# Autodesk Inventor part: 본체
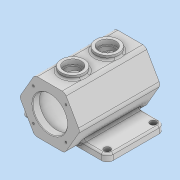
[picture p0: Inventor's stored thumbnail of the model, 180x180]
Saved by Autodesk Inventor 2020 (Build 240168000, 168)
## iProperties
Created: 2021-06
Part Number: 본체
Material: 일반
Document SubType Name: Modeling
Designer: MIRAE
Density: 1 g/cm^3
Appearance: 기본값
Mass: 553.662 g
Surface Area: 1102.91 cm^2
Volume: 553.662 cm^3
Author: MIRAE
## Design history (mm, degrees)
sketch "스케치5"
  geometry: L1 (0, 70)-(52.5, 70); L2 (52.5, 70)-(52.5, -70); L3 (52.5, -70)-(0, -70); L4 (0, -70)-(0, 70); L5 (30, 70)-(30, 58); L6 (30, 58)-(37.5, 58); L7 (37.5, 58)-(37.5, -58); L8 (37.5, -58)-(30, -58); L9 (30, -58)-(30, -70); 2 further points
  constraints: 18 end point, 4 perpendicular, 4 point on line, 2 parallel, 1 coincident, 1 horizontal, 1 midpoint, 1 vertical
  dimensions: "d13" = 105 diameter of L2 L4; "d14" = 140 distance of L1.end L2.end; "d15" = 60 diameter of L5 L4; "d16" = 75 diameter of L7 L4; "d17" = 12 distance between parallel lines of L6 L1; "d18" = 12 distance between parallel lines of L3 L8
revolve "회전2" sketch "스케치5" stored, may be unused: angle "d19" = 90 deg
sketch "스케치6" dims "d20" = 105
  geometry: L1 (52.5, 0)-(26.25, -45.466); L2 (26.25, -45.466)-(-26.25, -45.466); L3 (-26.25, -45.466)-(-52.5, 0); L4 (-52.5, 0)-(-26.25, 45.466); L5 (-26.25, 45.466)-(26.25, 45.466); L6 (26.25, 45.466)-(52.5, 0); C1 r 52.5 at (0, 0) reference; 13 further points
  constraints: 12 end point, 2 coincident, 1 horizontal, 16 other
extrude "돌출2" cut sketch "스케치6" extent not by distance; stored distance "d21" = 0; taper "d22" = 0 deg
node "작업 평면1"
sketch "스케치7"
  geometry: L1 (75, 45)-(-75, 45); L2 (-75, 45)-(-75, -55); L3 (-75, -55)-(75, -55); L4 (75, -55)-(75, 45); L5 (75, 45)-(-75, -55); L6 (-75, 45)-(75, -55); L7 (-26.25, 70)-(26.25, 70) reference; 3 further points
  constraints: 12 end point, 3 midpoint, 2 parallel, 1 horizontal, 1 perpendicular, 1 vertical alignment
  dimensions: "d24" = 150 distance of L3.end L2.end; "d25" = 100 distance of L2.end L1.end; "d26" = 25 distance between parallel lines of L7 L1
extrude "돌출3" join sketch "스케치7" distance "d27" = 12; taper "d28" = 0 deg
sketch "스케치10"
  geometry: L1 (26.25, -45.466)-(54.534, -17.182); L2 (26.25, -45.466)-(66.25, -45.466); C1 r 40 at (26.25, -45.466); 2 further points
  constraints: 4 end point, 2 coincident, 1 centre point, 1 equal length, 1 horizontal
  dimensions: "d43" = 80 diameter of C1; "d44" = 40 distance of L1.start L1.end; "d45" = 45 deg angle of L2 L1
hole "구멍2" sketch "스케치10" at (54.534, -17.182) diameter "d46" = 3.45873; stored, may be unused: countersink angle "d50" = 90 deg, drill point angle "d52" = 118 deg; dims "d47" = 8, "d48" = 30, "d49" = 8, "d51" = 10
sketch "스케치11" dims "d56" = 80
  geometry: L1 (26.25, 45.466)-(26.25, 85.466); 2 further points
  constraints: 2 coincident, 2 end point, 1 vertical, 1 vertical alignment, 2 other
hole "구멍3" sketch "스케치11" at (26.25, 85.466) diameter "d57" = 3.45873; stored, may be unused: countersink angle "d61" = 90 deg, drill point angle "d63" = 118 deg; dims "d58" = 8, "d59" = 30, "d60" = 8, "d62" = 10
fillet "모깎기1" dims "d67" = 10
sketch "스케치12"
  geometry: L1 (-58.005, 25.503)-(-58.005, -15.503); L2 (-58.005, -15.503)-(-63.995, -15.503); L3 (-63.995, -15.503)-(-63.995, 25.503); L4 (-63.995, 25.503)-(-58.005, 25.503); L5 (-58.005, 25.503)-(-63.995, -15.503); L6 (-65, -45)-(65, -45) reference; L7 (-75, 45)-(-75, -35) reference; 2 further points
  constraints: 2 end point, 1 midpoint, 2 other
  dimensions: "d68" = 50 distance from line of L6 point (-61, 5); "d69" = 14 distance from line of point (-61, 5) L7
feature "엠보싱1" sketch "스케치12" dims "d13" = 105, "d14" = 140, "d15" = 60, "d16" = 75, "d17" = 12, "d18" = 12, "d20" = 105, "d70" = 0.5, "d71" = 0
fillet "모깎기2" dims "d72" = 8
fillet "모깎기3" dims "d73" = 3
fillet "모깎기4" dims "d74" = 3
fillet "모깎기5" dims "d75" = 5
chamfer "모따기1" distance "d76" = 1; stored, may be unused: second distance "d77" = 2, angle "d78" = 45 deg
sketch "스케치13"
  geometry: L1 (65, 55)-(-65, 55) reference; L2 (75, -35)-(75, 45) reference; L3 (-65, -45)-(65, -45) reference; L4 (-75, 45)-(-75, -35) reference; A1 r 10 centre (-65, 45) between (-65, 55) and (-75, 45) reference; A2 r 10 centre (65, 45) between (75, 45) and (65, 55) reference; A3 r 10 centre (65, -35) between (65, -45) and (75, -35) reference; A4 r 10 centre (-65, -35) between (-75, -35) and (-65, -45) reference; 5 further points
  constraints: 4 coincident
hole "구멍4" sketch "스케치13" at (-65, -35), (-65, 45), (65, 45), (65, -35) diameter "d79" = 11; stored, may be unused: countersink angle "d83" = 90 deg, drill point angle "d85" = 118 deg; dims "d80" = 8, "d81" = 30, "d82" = 8, "d84" = 10
node "작업 평면5"
sketch "스케치14"
  geometry: L1 (-21.631, 70)-(21.631, 70) reference; C1 r 20 at (0, 30); C2 r 20 at (0, -30); 1 further point
  constraints: 2 centre point, 2 vertical alignment
  dimensions: "d87" = 40 diameter of C1; "d88" = 40 diameter of C2; "d89" = 40 distance from line of C1.centre L1; "d90" = 60 distance of C2.centre C1.centre
extrude "돌출5" join sketch "스케치14" stored distance "d91" = 10; taper "d92" = 0 deg
sketch "스케치15" dims "d24" = 150, "d25" = 100, "d26" = 25
  geometry: C1 r 20 at (0, 0) reference; C2 r 20 at (0, 60) reference; 3 further points
  constraints: 2 coincident
hole "구멍5" sketch "스케치15" at (0, 0), (0, 60) diameter "d93" = 25; stored, may be unused: countersink angle "d97" = 90 deg, drill point angle "d99" = 118 deg; dims "d94" = 8, "d95" = 30, "d96" = 8, "d98" = 30
fillet "모깎기6" dims "d100" = 3
chamfer "모따기2" distance "d101" = 1; stored, may be unused: second distance "d102" = 2, angle "d103" = 45 deg
node "솔리드2"
pattern_circular "원형 패턴1" dims angle "d54" = 360 deg
pattern_circular "원형 패턴2" dims angle "d65" = 360 deg
node "투영된 루프1"
feature "A9D066F2-1C7D-4E18-AEED-F7BC21143FA4" dims "d57" = 3.45873, "d58" = 8, "d59" = 30, "d60" = 8, "d61" = 90 deg, "d62" = 10, "d63" = 118 deg
other parameters: "d86" = 52.5
